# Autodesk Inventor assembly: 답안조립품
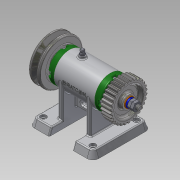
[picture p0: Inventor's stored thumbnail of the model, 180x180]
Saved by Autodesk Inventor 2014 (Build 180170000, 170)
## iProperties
Created: 2016-07
Part Number: 답안조립품
Document SubType Name: Assembly
Designer: net
Author: net
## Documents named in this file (16)
- C:\Users\net\Desktop\460707V1011\답안조립품.iam
- C:\Users\net\Desktop\460707V1011\V벨트풀리.ipt
- C:\Users\net\Desktop\460707V1011\너트 M 8.ipt
- C:\Users\net\Desktop\460707V1011\니플 M 6 x 0.75.ipt
- C:\Users\net\Desktop\460707V1011\베어링 15 x 32 x 9.ipt
- C:\Users\net\Desktop\460707V1011\본체.ipt
- C:\Users\net\Desktop\460707V1011\볼트 M 6 x 8.ipt
- C:\Users\net\Desktop\460707V1011\볼트 M4 x 12.ipt
- C:\Users\net\Desktop\460707V1011\스퍼기어.ipt
- C:\Users\net\Desktop\460707V1011\스프링와셔 8.ipt
- C:\Users\net\Desktop\460707V1011\오일 실 15 25 7.ipt
- C:\Users\net\Desktop\460707V1011\와셔 6x11.5.ipt
- C:\Users\net\Desktop\460707V1011\와셔 8x17.ipt
- C:\Users\net\Desktop\460707V1011\축.ipt
- C:\Users\net\Desktop\460707V1011\커버.ipt
- C:\Users\net\Desktop\460707V1011\키 3 x 3 x 12.ipt
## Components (11 placed, 3 different names)
1. V벨트풀리:1
2. KS B 2023 6002 - 15 x 32 x 9:1
3. KS B 2023 6002 - 15 x 32 x 9:2
4. ISO 4762 M4 x 12:1
5. ISO 4762 M4 x 12:3
6. ISO 4762 M4 x 12:4
7. ISO 4762 M4 x 12:5
8. ISO 4762 M4 x 12:2
9. ISO 4762 M4 x 12:6
10. ISO 4762 M4 x 12:7
11. ISO 4762 M4 x 12:8
